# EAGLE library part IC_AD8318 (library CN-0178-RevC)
1 MHz to 8 GHz, 70 dB Logarithmic Detector/Controller
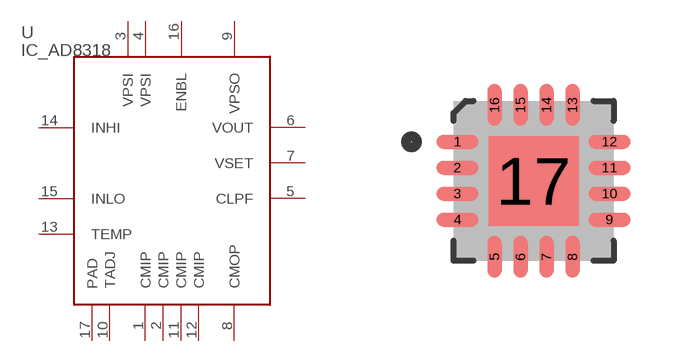
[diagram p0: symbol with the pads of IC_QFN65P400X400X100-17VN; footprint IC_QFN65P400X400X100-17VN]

Designator prefix U

## IC_AD8318_LFCSP_VQ  [IC_QFN65P400X400X100-17VN]
1  CMIP  pas
2  CMIP  pas
3  VPSI  pas
4  VPSI  pas
5  CLPF  pas
6  VOUT  pas
7  VSET  pas
8  CMOP  pas
9  VPSO  pas
10  TADJ  pas
11  CMIP  pas
12  CMIP  pas
13  TEMP  pas
14  INHI  pas
15  INLO  pas
16  ENBL  pas
17  PAD

## Footprint IC_QFN65P400X400X100-17VN (pad centres in mm)
(QFN-17) 0.65mm pitch; 4.00mm L X 4.00mm W X 1.00mm H body w/thermal tab; JEDEC MO-220VGGC
smd 1.05 x 0.35: 1 -1.9,0.975; 2 -1.9,0.325; 3 -1.9,-0.325; 4 -1.9,-0.975; 9 1.9,-0.975; 10 1.9,-0.325; 11 1.9,0.325; 12 1.9,0.975
smd 0.35 x 1.05: 5 -0.975,-1.9; 6 -0.325,-1.9; 7 0.325,-1.9; 8 0.975,-1.9; 13 0.975,1.9; 14 0.325,1.9; 15 -0.325,1.9; 16 -0.975,1.9
smd 2.25 x 2.25: 17 0,0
